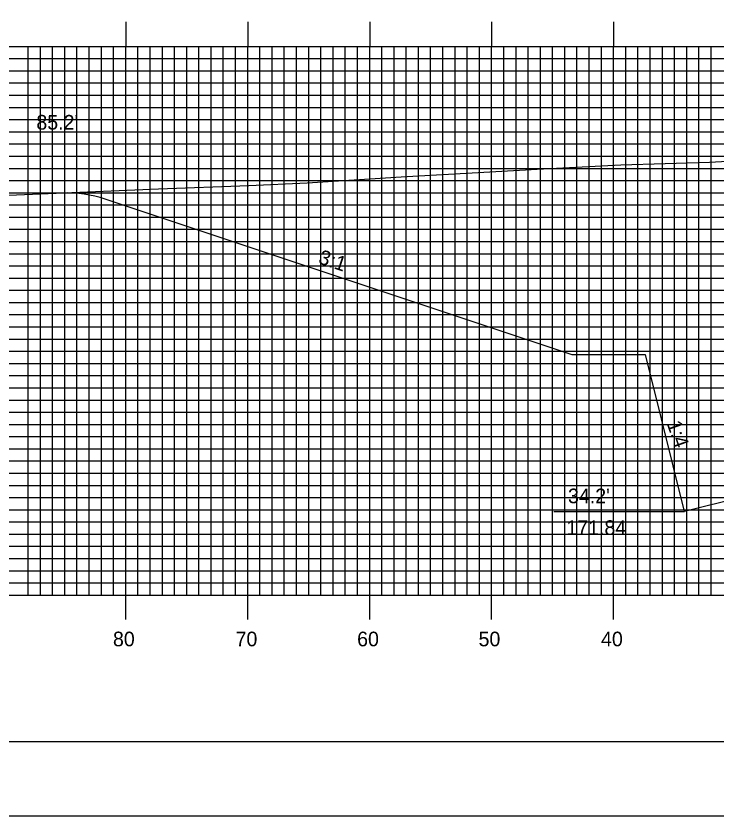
# Model space of a CAD drawing. Extents: x 1795633 to 1795976, y 442591 to 442811.
# Drawn here: x 1795709.9 to 1795767.4, y 442590.5 to 442656.2 of the extents above; entities that cross this region are included whole.
import ezdxf

# ---------------------------------------------------------------- set-up
doc = ezdxf.new("R2010")
doc.units = 0
for name, color, linetype in [('ANNOTATION', 7, 'Continuous'), ('BORDER', 7, 'Continuous'), ('D_Roadway_SlopeLines', 7, 'Continuous'), ('D_Text_Standard', 7, 'Continuous'), ('H_V ANNOTATION', 7, 'Continuous'), ('MAJOR', 7, 'Continuous'), ('MINOR', 7, 'Continuous'), ('PDRAIN', 7, 'Continuous'), ('PLOT BOUNDARY', 7, 'Continuous'), ('S_Roadway_Centerline', 7, 'Continuous')]:
    doc.layers.add(name, color=color, linetype=linetype)

msp = doc.modelspace()

# ---------------------------------------------------------------- linework, layer by layer
at = {"layer": 'BORDER'}
msp.add_lwpolyline([(1795649.279, 442596.665), (1795969.279, 442596.665), (1795969.279, 442806.665), (1795649.279, 442806.665)], close=True, dxfattribs=at)
at = {"layer": 'D_Roadway_SlopeLines'}
msp.add_line((1795764.705, 442615.507), (1795761.865, 442626.868), dxfattribs=at)
for points in [[(1795761.865, 442626.868), (1795761.49, 442628.365), (1795755.49, 442628.365), (1795717.201, 442641.128)], [(1795778.879, 442619.05), (1795764.705, 442615.507)]]:
    msp.add_lwpolyline(points, dxfattribs=at)
msp.add_arc((1795714.004, 442631.536), 10.111, 71.56505, 91.80242, dxfattribs=at)
at = {"layer": 'MAJOR'}
for p, q in [((1795718.879, 442655.669), (1795718.879, 442653.665)), ((1795728.879, 442655.669), (1795728.879, 442653.665)), ((1795738.879, 442655.669), (1795738.879, 442653.665)), ((1795748.879, 442655.669), (1795748.879, 442653.665)), ((1795758.879, 442655.669), (1795758.879, 442653.665)), ((1795658.879, 442653.665), (1795938.879, 442653.665)), ((1795658.879, 442653.665), (1795938.879, 442653.665)), ((1795718.879, 442608.665), (1795718.879, 442653.665)), ((1795728.879, 442608.665), (1795728.879, 442653.665)), ((1795738.879, 442608.665), (1795738.879, 442653.665)), ((1795748.879, 442608.665), (1795748.879, 442653.665)), ((1795758.879, 442608.665), (1795758.879, 442653.665)), ((1795658.879, 442648.665), (1795938.879, 442648.665)), ((1795658.879, 442643.665), (1795938.879, 442643.665)), ((1795658.879, 442638.665), (1795938.879, 442638.665)), ((1795658.879, 442633.665), (1795938.879, 442633.665)), ((1795658.879, 442628.665), (1795938.879, 442628.665)), ((1795658.879, 442623.665), (1795938.879, 442623.665)), ((1795658.879, 442618.665), (1795938.879, 442618.665)), ((1795658.879, 442613.665), (1795938.879, 442613.665)), ((1795658.879, 442608.665), (1795938.879, 442608.665)), ((1795658.879, 442608.665), (1795938.879, 442608.665)), ((1795718.879, 442606.661), (1795718.879, 442608.665)), ((1795728.879, 442606.661), (1795728.879, 442608.665)), ((1795738.879, 442606.661), (1795738.879, 442608.665)), ((1795748.879, 442606.661), (1795748.879, 442608.665)), ((1795758.879, 442606.661), (1795758.879, 442608.665))]:
    msp.add_line(p, q, dxfattribs=at)
at = {"layer": 'MINOR'}
for p, q in [((1795710.879, 442608.665), (1795710.879, 442653.665)), ((1795711.879, 442608.665), (1795711.879, 442653.665)), ((1795712.879, 442608.665), (1795712.879, 442653.665)), ((1795713.879, 442608.665), (1795713.879, 442653.665)), ((1795714.879, 442608.665), (1795714.879, 442653.665)), ((1795715.879, 442608.665), (1795715.879, 442653.665)), ((1795716.879, 442608.665), (1795716.879, 442653.665)), ((1795717.879, 442608.665), (1795717.879, 442653.665)), ((1795719.879, 442608.665), (1795719.879, 442653.665)), ((1795720.879, 442608.665), (1795720.879, 442653.665)), ((1795721.879, 442608.665), (1795721.879, 442653.665)), ((1795722.879, 442608.665), (1795722.879, 442653.665)), ((1795723.879, 442608.665), (1795723.879, 442653.665)), ((1795724.879, 442608.665), (1795724.879, 442653.665)), ((1795725.879, 442608.665), (1795725.879, 442653.665)), ((1795726.879, 442608.665), (1795726.879, 442653.665)), ((1795727.879, 442608.665), (1795727.879, 442653.665)), ((1795729.879, 442608.665), (1795729.879, 442653.665)), ((1795730.879, 442608.665), (1795730.879, 442653.665)), ((1795731.879, 442608.665), (1795731.879, 442653.665)), ((1795732.879, 442608.665), (1795732.879, 442653.665)), ((1795733.879, 442608.665), (1795733.879, 442653.665)), ((1795734.879, 442608.665), (1795734.879, 442653.665)), ((1795735.879, 442608.665), (1795735.879, 442653.665)), ((1795736.879, 442608.665), (1795736.879, 442653.665)), ((1795737.879, 442608.665), (1795737.879, 442653.665)), ((1795739.879, 442608.665), (1795739.879, 442653.665)), ((1795740.879, 442608.665), (1795740.879, 442653.665)), ((1795741.879, 442608.665), (1795741.879, 442653.665)), ((1795742.879, 442608.665), (1795742.879, 442653.665)), ((1795743.879, 442608.665), (1795743.879, 442653.665)), ((1795744.879, 442608.665), (1795744.879, 442653.665)), ((1795745.879, 442608.665), (1795745.879, 442653.665)), ((1795746.879, 442608.665), (1795746.879, 442653.665)), ((1795747.879, 442608.665), (1795747.879, 442653.665)), ((1795749.879, 442608.665), (1795749.879, 442653.665)), ((1795750.879, 442608.665), (1795750.879, 442653.665)), ((1795751.879, 442608.665), (1795751.879, 442653.665)), ((1795752.879, 442608.665), (1795752.879, 442653.665)), ((1795753.879, 442608.665), (1795753.879, 442653.665)), ((1795754.879, 442608.665), (1795754.879, 442653.665)), ((1795755.879, 442608.665), (1795755.879, 442653.665)), ((1795756.879, 442608.665), (1795756.879, 442653.665)), ((1795757.879, 442608.665), (1795757.879, 442653.665)), ((1795759.879, 442608.665), (1795759.879, 442653.665)), ((1795760.879, 442608.665), (1795760.879, 442653.665)), ((1795761.879, 442608.665), (1795761.879, 442653.665)), ((1795762.879, 442608.665), (1795762.879, 442653.665)), ((1795763.879, 442608.665), (1795763.879, 442653.665)), ((1795764.879, 442608.665), (1795764.879, 442653.665)), ((1795765.879, 442608.665), (1795765.879, 442653.665)), ((1795766.879, 442608.665), (1795766.879, 442653.665)), ((1795658.879, 442652.665), (1795938.879, 442652.665)), ((1795658.879, 442651.665), (1795938.879, 442651.665)), ((1795658.879, 442650.665), (1795938.879, 442650.665)), ((1795658.879, 442649.665), (1795938.879, 442649.665)), ((1795658.879, 442647.665), (1795938.879, 442647.665)), ((1795658.879, 442646.665), (1795938.879, 442646.665)), ((1795658.879, 442645.665), (1795938.879, 442645.665)), ((1795658.879, 442644.665), (1795938.879, 442644.665)), ((1795658.879, 442642.665), (1795938.879, 442642.665)), ((1795658.879, 442641.665), (1795938.879, 442641.665)), ((1795658.879, 442640.665), (1795938.879, 442640.665)), ((1795658.879, 442639.665), (1795938.879, 442639.665)), ((1795658.879, 442637.665), (1795938.879, 442637.665)), ((1795658.879, 442636.665), (1795938.879, 442636.665)), ((1795658.879, 442635.665), (1795938.879, 442635.665)), ((1795658.879, 442634.665), (1795938.879, 442634.665)), ((1795658.879, 442632.665), (1795938.879, 442632.665)), ((1795658.879, 442631.665), (1795938.879, 442631.665)), ((1795658.879, 442630.665), (1795938.879, 442630.665)), ((1795658.879, 442629.665), (1795938.879, 442629.665)), ((1795658.879, 442627.665), (1795938.879, 442627.665)), ((1795658.879, 442626.665), (1795938.879, 442626.665)), ((1795658.879, 442625.665), (1795938.879, 442625.665)), ((1795658.879, 442624.665), (1795938.879, 442624.665)), ((1795658.879, 442622.665), (1795938.879, 442622.665)), ((1795658.879, 442621.665), (1795938.879, 442621.665)), ((1795658.879, 442620.665), (1795938.879, 442620.665)), ((1795658.879, 442619.665), (1795938.879, 442619.665)), ((1795658.879, 442617.665), (1795938.879, 442617.665)), ((1795658.879, 442616.665), (1795938.879, 442616.665)), ((1795658.879, 442615.665), (1795938.879, 442615.665)), ((1795658.879, 442614.665), (1795938.879, 442614.665)), ((1795658.879, 442612.665), (1795938.879, 442612.665)), ((1795658.879, 442611.665), (1795938.879, 442611.665)), ((1795658.879, 442610.665), (1795938.879, 442610.665)), ((1795658.879, 442609.665), (1795938.879, 442609.665))]:
    msp.add_line(p, q, dxfattribs=at)
at = {"layer": 'PDRAIN'}
msp.add_line((1795753.982, 442615.507), (1795764.705, 442615.507), dxfattribs=at)
at = {"layer": 'PLOT BOUNDARY'}
msp.add_lwpolyline([(1795633.092, 442590.547), (1795973.092, 442590.547), (1795973.092, 442810.547), (1795633.092, 442810.547)], close=True, dxfattribs=at)
at = {"layer": 'S_Roadway_Centerline'}
msp.add_lwpolyline([(1795703.44, 442641.209), (1795721.553, 442641.975), (1795728.975, 442642.255), (1795733.766, 442642.477), (1795741.468, 442642.963), (1795752.624, 442643.595), (1795759.475, 442643.964), (1795766.73, 442644.174), (1795771.712, 442644.431), (1795779.336, 442644.754), (1795791.365, 442645.425), (1795791.458, 442645.427), (1795810.49, 442645.796), (1795814.769, 442645.964), (1795823.19, 442645.949), (1795827.655, 442645.966), (1795830.161, 442645.986), (1795841.531, 442646.19), (1795849.119, 442646.362), (1795853.354, 442646.443), (1795862.992, 442646.707)], dxfattribs=at)

# ---------------------------------------------------------------- texts
at = {"layer": 'ANNOTATION'}
for s, rotation, p in [('3:1', 341.56505, (1795734.604, 442635.89)), ('3:1', 341.56505, (1795734.604, 442635.89)), ('1:4', 289.48399, (1795763.225, 442622.731))]:
    msp.add_text(s, height=1.2, rotation=rotation, dxfattribs=at).set_placement(p)
for s, p in [("34.2'", (1795755.143, 442616.199)), ('171.84', (1795755.009, 442613.599))]:
    msp.add_text(s, height=1.2, dxfattribs=at).set_placement(p)
at = {"layer": 'D_Text_Standard'}
msp.add_text("85.2'", height=1.2, dxfattribs=at).set_placement((1795711.551, 442646.841))
at = {"layer": 'H_V ANNOTATION'}
for s, p in [('80', (1795717.83, 442604.465)), ('70', (1795727.883, 442604.465)), ('60', (1795737.851, 442604.465)), ('50', (1795747.808, 442604.465)), ('40', (1795757.851, 442604.465))]:
    msp.add_text(s, height=1.2, dxfattribs=at).set_placement(p)

doc.saveas('drawing.dxf')
